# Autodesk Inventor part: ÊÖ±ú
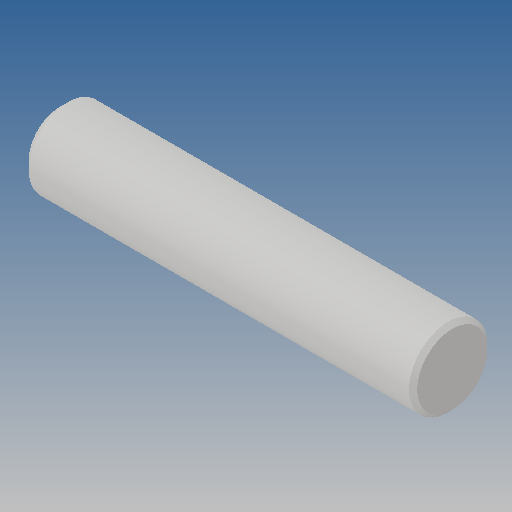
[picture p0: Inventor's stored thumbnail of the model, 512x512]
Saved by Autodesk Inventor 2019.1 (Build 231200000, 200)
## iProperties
Created: 2012-10
Part Number: ÊÖ±ú
Material: Ogólny
Document SubType Name: Modeling
Designer: CADENGINEERING4
Density: 1 g/cm^3
Appearance: Domyślna
Author: CADENGINEERING4
Revision Number: ÈÎºÎ
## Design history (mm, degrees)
feature "Ðý×ª1"
node "Bryła1"
